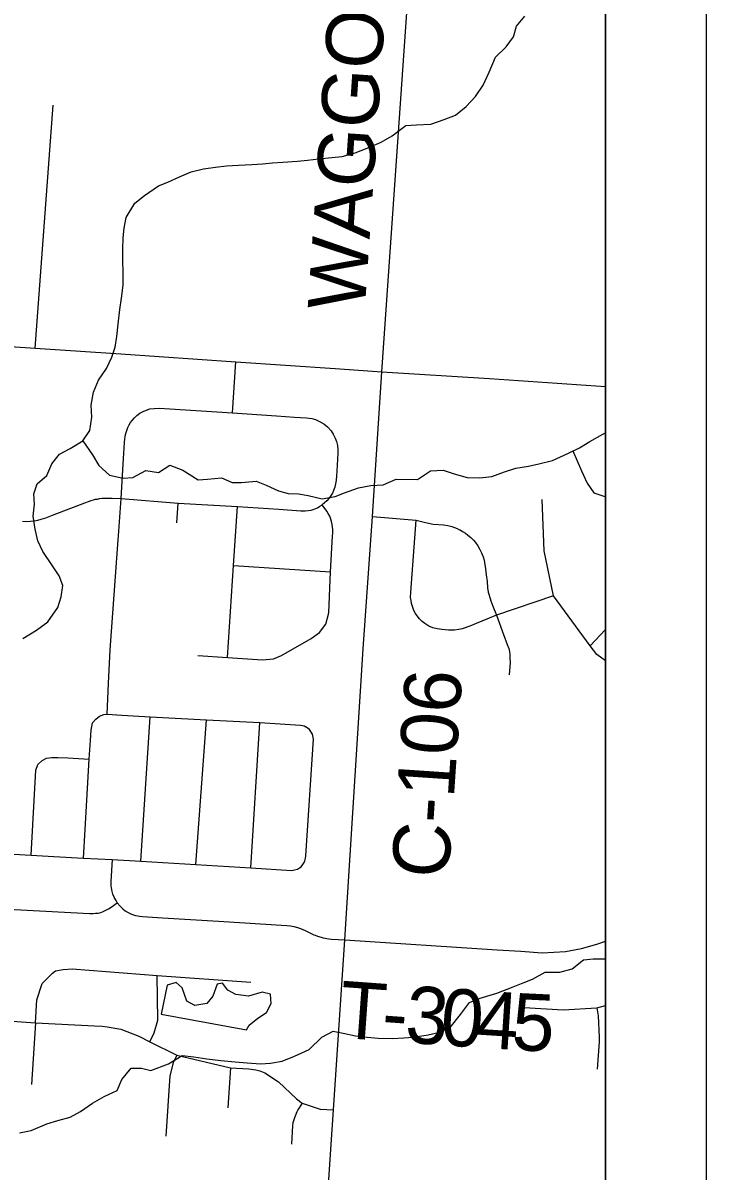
# Model space of a CAD drawing. Extents: x 208586767.6 to 208586821.4, y -134301046.9 to -134301022.9.
# Drawn here: x 208586784.249 to 208586784.928, y -134301030.351 to -134301029.209 of the extents above; entities that cross this region are included whole.
import ezdxf

# ---------------------------------------------------------------- set-up
doc = ezdxf.new("R2010")
doc.units = 0
for name, color, linetype in [('GM_X_Corporation', 7, 'Continuous'), ('GM_X_County_Road', 7, 'Continuous'), ('GM_X_County_Road_Text', 7, 'Continuous'), ('GM_X_Minor_Lake', 7, 'Continuous'), ('GM_X_Minor_River', 7, 'Continuous'), ('GM_X_Township_Road', 7, 'Continuous'), ('GM_X_Township_Road_Text', 7, 'Continuous'), ('SH_Data', 7, 'Continuous')]:
    doc.layers.add(name, color=color, linetype=linetype)

msp = doc.modelspace()

# ---------------------------------------------------------------- linework, layer by layer
at = {"layer": 'GM_X_Corporation'}
msp.add_lwpolyline([(208586780.4561, -134301030.8407), (208586784.8283, -134301030.8407), (208586784.8283, -134301027.3051), (208586784.2616, -134301027.2694), (208586783.9036, -134301027.2474), (208586783.5221, -134301027.2233), (208586782.8221, -134301027.178), (208586782.72, -134301027.1729), (208586782.648, -134301027.1691), (208586782.6378, -134301027.1684), (208586782.6086, -134301027.1669), (208586782.1685, -134301027.1422), (208586781.98, -134301027.1295), (208586781.8736, -134301027.1231), (208586781.8549, -134301027.122), (208586781.8329, -134301027.1207), (208586781.7344, -134301027.1148), (208586781.7056, -134301027.1139), (208586781.6677, -134301027.1118), (208586781.2713, -134301027.0897)], dxfattribs=at)
at = {"layer": 'GM_X_County_Road'}
for points in [[(208586784.6058, -134301029.5557), (208586784.6478, -134301028.9502), (208586784.6497, -134301028.9173)], [(208586783.2684, -134301029.5377), (208586783.3875, -134301029.5464), (208586783.5253, -134301029.5557), (208586783.5863, -134301029.5603), (208586783.6494, -134301029.5646), (208586783.6822, -134301029.5661), (208586783.7371, -134301029.5592), (208586783.7717, -134301029.5486), (208586783.7999, -134301029.5404), (208586783.842, -134301029.5277), (208586783.8725, -134301029.5192), (208586783.899, -134301029.5131), (208586783.925, -134301029.5105), (208586783.9583, -134301029.512), (208586783.9759, -134301029.5131), (208586784.0981, -134301029.5214), (208586784.1958, -134301029.5279), (208586784.261, -134301029.5322), (208586784.346, -134301029.5381), (208586784.4606, -134301029.5458), (208586784.5592, -134301029.5524), (208586784.6058, -134301029.5557), (208586784.7129, -134301029.5625), (208586784.8283, -134301029.5704)], [(208586784.555, -134301030.3295), (208586784.5576, -134301030.2902), (208586784.5689, -134301030.1211), (208586784.5873, -134301029.8315), (208586784.5965, -134301029.6999), (208586784.6058, -134301029.5557)], [(208586784.5262, -134301030.8407), (208586784.5315, -134301030.7681), (208586784.5315, -134301030.7336), (208586784.5353, -134301030.6564), (208586784.5412, -134301030.5475), (208586784.5437, -134301030.5064), (208586784.5449, -134301030.4836), (208586784.555, -134301030.3295)]]:
    msp.add_lwpolyline(points, dxfattribs=at)
at = {"layer": 'GM_X_Minor_Lake'}
for points in [[(208586784.4712, -134301030.2107), (208586784.4739, -134301030.2058), (208586784.4823, -134301030.199), (208586784.4911, -134301030.1933), (208586784.4957, -134301030.1843), (208586784.495, -134301030.1751), (208586784.4867, -134301030.1732), (208586784.473, -134301030.1769), (208586784.4605, -134301030.1753), (208586784.4525, -134301030.1711), (208586784.4472, -134301030.1642), (208586784.4419, -134301030.165), (208586784.4377, -134301030.1771), (208586784.4316, -134301030.1843), (208586784.4198, -134301030.1865), (208586784.4118, -134301030.1819), (208586784.407, -134301030.1689), (208586784.4013, -134301030.1636), (208586784.3922, -134301030.1662), (208586784.3863, -134301030.195)], [(208586784.3863, -134301030.195), (208586784.4712, -134301030.2107)]]:
    msp.add_lwpolyline(points, dxfattribs=at)
at = {"layer": 'GM_X_Minor_River'}
for points in [[(208586784.3404, -134301029.5314), (208586784.3423, -134301029.5208), (208586784.3435, -134301029.5083), (208586784.3452, -134301029.4938), (208586784.3467, -134301029.4825), (208586784.3483, -134301029.4696), (208586784.3484, -134301029.4567), (208586784.3481, -134301029.4453), (208586784.3482, -134301029.4339), (208586784.3486, -134301029.4225), (208586784.3495, -134301029.413), (208586784.3514, -134301029.4024), (208586784.3599, -134301029.3881), (208586784.3698, -134301029.3805), (208586784.3835, -134301029.3707), (208586784.393, -134301029.367), (208586784.4044, -134301029.3618), (208586784.4162, -134301029.3569), (208586784.4284, -134301029.3539), (208586784.4402, -134301029.3521), (208586784.4512, -134301029.351), (208586784.4633, -134301029.3503), (208586784.4766, -134301029.3497), (208586784.4872, -134301029.349), (208586784.4971, -134301029.3479), (208586784.5074, -134301029.3472), (208586784.5218, -134301029.3461), (208586784.5317, -134301029.3451), (208586784.5431, -134301029.344), (208586784.556, -134301029.3425), (208586784.5662, -134301029.3415), (208586784.5792, -134301029.3381), (208586784.5913, -134301029.3333), (208586784.605, -134301029.3273), (208586784.6161, -134301029.3209), (208586784.6298, -134301029.3107), (208586784.6401, -134301029.31), (208586784.6545, -134301029.3094), (208586784.6678, -134301029.3049), (208586784.6792, -134301029.3004), (208586784.6895, -134301029.2917), (208586784.6991, -134301029.2819), (208586784.7067, -134301029.2706), (208586784.7125, -134301029.2577), (208586784.7187, -134301029.2429), (208586784.7294, -134301029.2324), (208586784.7366, -134301029.2226), (208586784.7397, -134301029.212), (208586784.7481, -134301029.2018)], [(208586784.2486, -134301029.8211), (208586784.2623, -134301029.8129), (208586784.2734, -134301029.8046), (208586784.2833, -134301029.7902), (208586784.2868, -134301029.7796), (208586784.2884, -134301029.7686), (208586784.2847, -134301029.7587), (208586784.2783, -134301029.7488), (208586784.2685, -134301029.7347), (208586784.2636, -134301029.7241), (208586784.261, -134301029.7123), (208586784.2589, -134301029.6994), (208586784.2601, -134301029.6876), (208586784.2597, -134301029.6774), (208586784.2628, -134301029.6672), (208586784.2724, -134301029.6589), (208586784.2774, -134301029.6475), (208586784.285, -134301029.6377), (208586784.2957, -134301029.6321), (208586784.3083, -134301029.6245), (208586784.3152, -134301029.6143), (208586784.3172, -134301029.6011), (208586784.3165, -134301029.5889), (208586784.3188, -134301029.576), (208586784.3238, -134301029.5643), (208586784.3319, -134301029.5526), (208586784.3373, -134301029.5412), (208586784.3404, -134301029.5314)], [(208586784.3083, -134301029.6245), (208586784.3181, -134301029.6383), (208586784.3241, -134301029.6489), (208586784.335, -134301029.6585), (208586784.3483, -134301029.6616), (208586784.3582, -134301029.6609), (208586784.3711, -134301029.6541), (208586784.3836, -134301029.6561), (208586784.395, -134301029.6486), (208586784.4079, -134301029.6536), (208586784.423, -134301029.6632), (208586784.4325, -134301029.6625), (208586784.4462, -134301029.6614), (208586784.4568, -134301029.666), (208586784.4663, -134301029.6661), (208586784.4807, -134301029.6647), (208586784.4906, -134301029.6685), (208586784.503, -134301029.6743), (208586784.5125, -134301029.677), (208586784.5228, -134301029.6774), (208586784.5326, -134301029.679), (208586784.5463, -134301029.6821), (208586784.5592, -134301029.6799), (208586784.5687, -134301029.6762), (208586784.5824, -134301029.6713), (208586784.5949, -134301029.6691), (208586784.6071, -134301029.6684), (208586784.62, -134301029.6628), (208586784.6413, -134301029.663), (208586784.6542, -134301029.6543), (208586784.6668, -134301029.6536), (208586784.6777, -134301029.6575), (208586784.6906, -134301029.661), (208586784.7031, -134301029.6614), (208586784.7153, -134301029.66), (208586784.7278, -134301029.6555), (208586784.7389, -134301029.6518), (208586784.7518, -134301029.6496), (208586784.7621, -134301029.6474), (208586784.7754, -134301029.644), (208586784.7913, -134301029.6369), (208586784.8024, -134301029.6313), (208586784.8127, -134301029.6253), (208586784.8256, -134301029.6178), (208586784.8283, -134301029.6164)], [(208586784.7959, -134301029.6346), (208586784.8045, -134301029.6544), (208586784.8101, -134301029.6666), (208586784.8165, -134301029.6761), (208586784.8275, -134301029.68), (208586784.8283, -134301029.6797)], [(208586784.2452, -134301030.3129), (208586784.2569, -134301030.3107), (208586784.2725, -134301030.304), (208586784.2836, -134301030.3006), (208586784.2957, -134301030.2973), (208586784.306, -134301030.2917), (208586784.3178, -134301030.2834), (208586784.3296, -134301030.277), (208586784.3426, -134301030.271), (208586784.3472, -134301030.26), (208586784.3564, -134301030.2487), (208586784.3666, -134301030.2488), (208586784.3761, -134301030.2511), (208586784.3936, -134301030.2444), (208586784.4073, -134301030.2361), (208586784.4187, -134301030.2373), (208586784.4316, -134301030.2393), (208586784.4456, -134301030.2409), (208586784.46, -134301030.2425), (208586784.4718, -134301030.2433), (208586784.4851, -134301030.2445), (208586784.4949, -134301030.2438), (208586784.5067, -134301030.2416), (208586784.5189, -134301030.2368), (208586784.5334, -134301030.23), (208586784.546, -134301030.218), (208586784.5574, -134301030.2119), (208586784.5672, -134301030.2139), (208586784.5797, -134301030.2166), (208586784.5911, -134301030.2178), (208586784.6021, -134301030.2187), (208586784.6162, -134301030.2191), (208586784.6276, -134301030.2184), (208586784.637, -134301030.2177), (208586784.6519, -134301030.2155), (208586784.6617, -134301030.2133), (208586784.6739, -134301030.2081), (208586784.6839, -134301030.1952), (208586784.6931, -134301030.1835), (208586784.7037, -134301030.179), (208586784.7201, -134301030.1742), (208586784.7364, -134301030.1679), (208586784.7463, -134301030.1637), (208586784.7558, -134301030.16), (208586784.7684, -134301030.1532), (208586784.7828, -134301030.1533), (208586784.795, -134301030.15), (208586784.8064, -134301030.1409), (208586784.8159, -134301030.1399), (208586784.8277, -134301030.1399), (208586784.8283, -134301030.1399)]]:
    msp.add_lwpolyline(points, dxfattribs=at)
at = {"layer": 'GM_X_Township_Road'}
for p, q in [((208586784.261, -134301029.5322), (208586784.2789, -134301029.2905)), ((208586784.4572, -134301029.5965), (208586784.4606, -134301029.5458)), ((208586784.4019, -134301029.7061), (208586784.4031, -134301029.6864)), ((208586784.4583, -134301029.7484), (208586784.5547, -134301029.7549)), ((208586784.8131, -134301029.8285), (208586784.8283, -134301029.8122)), ((208586784.3324, -134301029.8963), (208586784.3339, -134301029.8658)), ((208586784.366, -134301030.0426), (208586784.3754, -134301029.899)), ((208586784.4208, -134301030.046), (208586784.4312, -134301029.902)), ((208586784.4756, -134301030.0494), (208586784.4845, -134301029.9048)), ((208586784.3823, -134301030.1565), (208586784.4754, -134301030.163)), ((208586784.2612, -134301030.2037), (208586784.2574, -134301030.2651)), ((208586784.4551, -134301030.2483), (208586784.4525, -134301030.288))]:
    msp.add_line(p, q, dxfattribs=at)
for points in [[(208586784.3597, -134301029.6016), (208586784.3622, -134301029.5993), (208586784.3651, -134301029.5971), (208586784.369, -134301029.595), (208586784.3749, -134301029.5928), (208586784.3792, -134301029.5922), (208586784.3847, -134301029.592), (208586784.3948, -134301029.5927), (208586784.4572, -134301029.5965), (208586784.501, -134301029.5995), (208586784.5188, -134301029.6008), (208586784.5307, -134301029.6016), (208586784.5361, -134301029.6023), (208586784.5399, -134301029.6032), (208586784.5439, -134301029.6051), (208586784.5479, -134301029.6075), (208586784.5517, -134301029.6105), (208586784.5553, -134301029.6144), (208586784.5575, -134301029.6179), (208586784.5595, -134301029.6217), (208586784.5607, -134301029.6253), (208586784.5615, -134301029.629), (208586784.562, -134301029.6333), (208586784.562, -134301029.6369), (208586784.5609, -134301029.6546), (208586784.5606, -134301029.6593), (208586784.5602, -134301029.6636), (208586784.5598, -134301029.6673), (208586784.5589, -134301029.6705), (208586784.5578, -134301029.6738), (208586784.5566, -134301029.6766), (208586784.5553, -134301029.6786), (208586784.5535, -134301029.6816), (208586784.5511, -134301029.6843), (208586784.5464, -134301029.6883)], [(208586784.3464, -134301029.682), (208586784.3489, -134301029.642), (208586784.3496, -134301029.6316), (208586784.3499, -134301029.6263), (208586784.3502, -134301029.6224), (208586784.3504, -134301029.6205), (208586784.3508, -134301029.6183), (208586784.3513, -134301029.6162), (208586784.352, -134301029.6141), (208586784.3531, -134301029.6113), (208586784.3544, -134301029.6087), (208586784.3558, -134301029.6064), (208586784.3573, -134301029.6043), (208586784.3597, -134301029.6016)], [(208586784.2483, -134301029.7045), (208586784.2522, -134301029.7046), (208586784.2563, -134301029.7045), (208586784.2602, -134301029.7041), (208586784.2637, -134301029.7034), (208586784.2668, -134301029.7026), (208586784.2716, -134301029.701), (208586784.2781, -134301029.6985), (208586784.3102, -134301029.6861), (208586784.3138, -134301029.6847), (208586784.3165, -134301029.6838), (208586784.3188, -134301029.6831), (208586784.3208, -134301029.6827), (208586784.3229, -134301029.6824), (208586784.3249, -134301029.682), (208586784.3277, -134301029.6816), (208586784.3307, -134301029.6815), (208586784.3337, -134301029.6814), (208586784.3376, -134301029.6815), (208586784.3464, -134301029.682), (208586784.4031, -134301029.6864), (208586784.4623, -134301029.6898), (208586784.5033, -134301029.6926), (208586784.5251, -134301029.6943), (208586784.5295, -134301029.6943), (208586784.5325, -134301029.6939), (208586784.5356, -134301029.6934), (208586784.5385, -134301029.6924), (208586784.5417, -134301029.691), (208586784.5442, -134301029.6896), (208586784.5464, -134301029.6883)], [(208586784.3434, -134301029.723), (208586784.3437, -134301029.7189), (208586784.3464, -134301029.682)], [(208586784.8283, -134301029.8435), (208586784.8195, -134301029.8372), (208586784.8131, -134301029.8285), (208586784.7764, -134301029.7786), (208586784.7673, -134301029.7339), (208586784.7654, -134301029.6828)], [(208586784.4228, -134301029.838), (208586784.4521, -134301029.84), (208586784.4871, -134301029.8424), (208586784.4979, -134301029.8413), (208586784.5058, -134301029.8381), (208586784.5354, -134301029.8211), (208586784.5439, -134301029.8153), (208586784.55, -134301029.8068), (208586784.5529, -134301029.7956), (208586784.5547, -134301029.7549), (208586784.5568, -134301029.7193), (208586784.557, -134301029.7159), (208586784.5571, -134301029.713), (208586784.5568, -134301029.71), (208586784.5563, -134301029.7077), (208586784.5557, -134301029.7049), (208586784.555, -134301029.7024), (208586784.5539, -134301029.6994), (208586784.5525, -134301029.6969), (208586784.5509, -134301029.6945), (208586784.5464, -134301029.6883)], [(208586784.4521, -134301029.84), (208586784.4583, -134301029.7484), (208586784.4623, -134301029.6898)], [(208586784.5965, -134301029.6999), (208586784.6398, -134301029.7034), (208586784.6492, -134301029.7056)], [(208586784.7764, -134301029.7786), (208586784.7197, -134301029.7981), (208586784.7052, -134301029.8039), (208586784.6995, -134301029.8061), (208586784.6948, -134301029.8081), (208586784.6886, -134301029.8105), (208586784.6857, -134301029.8115), (208586784.6825, -134301029.8123), (208586784.6781, -134301029.8128), (208586784.672, -134301029.8129), (208586784.6654, -134301029.8123), (208586784.6609, -134301029.8117), (208586784.6565, -134301029.8105), (208586784.6524, -134301029.8088), (208586784.6485, -134301029.8063), (208586784.6458, -134301029.8042), (208586784.6433, -134301029.8016), (208586784.6408, -134301029.7986), (208586784.6393, -134301029.7963), (208586784.6377, -134301029.7932), (208586784.6362, -134301029.7894), (208586784.6354, -134301029.7865), (208586784.6349, -134301029.7835), (208586784.6344, -134301029.7804), (208586784.6346, -134301029.7751), (208586784.6398, -134301029.7034)], [(208586784.6492, -134301029.7056), (208586784.6567, -134301029.7074), (208586784.6671, -134301029.7081), (208586784.6713, -134301029.7089), (208586784.6753, -134301029.7098), (208586784.6808, -134301029.7117), (208586784.683, -134301029.7129), (208586784.6836, -134301029.7132), (208586784.6861, -134301029.7146), (208586784.689, -134301029.7165), (208586784.6914, -134301029.7183), (208586784.6944, -134301029.7208), (208586784.6969, -134301029.7233), (208586784.6988, -134301029.7256), (208586784.7013, -134301029.729), (208586784.7034, -134301029.7325), (208586784.705, -134301029.736), (208586784.7066, -134301029.7399), (208586784.7075, -134301029.7433), (208586784.708, -134301029.7454), (208586784.7088, -134301029.7518), (208586784.7096, -134301029.7578), (208586784.7104, -134301029.7646), (208586784.711, -134301029.7708), (208586784.7117, -134301029.775), (208586784.7125, -134301029.7782), (208586784.7142, -134301029.7837), (208586784.7162, -134301029.7891), (208586784.7197, -134301029.7981)], [(208586784.3339, -134301029.8658), (208586784.3356, -134301029.8324), (208586784.3434, -134301029.723)], [(208586784.7197, -134301029.7981), (208586784.7268, -134301029.8173), (208586784.7306, -134301029.827), (208586784.732, -134301029.8312), (208586784.7327, -134301029.8341), (208586784.7332, -134301029.8374), (208586784.7332, -134301029.8407), (208586784.7333, -134301029.8451), (208586784.7323, -134301029.8574)], [(208586784.3089, -134301030.0396), (208586784.3106, -134301030.0111), (208586784.3147, -134301029.9413), (208586784.3159, -134301029.9228), (208586784.3165, -134301029.9123), (208586784.3178, -134301029.9051), (208586784.3211, -134301029.9014), (208586784.325, -134301029.8983), (208586784.3293, -134301029.8967), (208586784.3324, -134301029.8963)], [(208586784.3324, -134301029.8963), (208586784.3472, -134301029.8973), (208586784.3754, -134301029.899), (208586784.4312, -134301029.902), (208586784.4845, -134301029.9048), (208586784.5248, -134301029.9074), (208586784.5268, -134301029.9078), (208586784.5284, -134301029.9082), (208586784.5295, -134301029.9087)], [(208586784.5254, -134301030.0482), (208586784.5273, -134301030.0461), (208586784.5285, -134301030.0442), (208586784.5293, -134301030.0423), (208586784.5299, -134301030.0397), (208586784.5301, -134301030.0373), (208586784.5378, -134301029.9212), (208586784.5369, -134301029.9165), (208586784.5339, -134301029.9118), (208586784.5295, -134301029.9087)], [(208586784.2569, -134301030.0366), (208586784.2616, -134301029.9523), (208586784.2637, -134301029.9464), (208586784.2678, -134301029.9425), (208586784.2721, -134301029.9404), (208586784.2774, -134301029.9396), (208586784.2834, -134301029.9396), (208586784.2933, -134301029.9398), (208586784.3147, -134301029.9413)], [(208586784.1509, -134301030.0527), (208586784.1554, -134301030.0465), (208586784.1606, -134301030.042), (208586784.1655, -134301030.0379), (208586784.1719, -134301030.035), (208586784.1784, -134301030.0332), (208586784.1865, -134301030.0327), (208586784.2569, -134301030.0366), (208586784.2794, -134301030.0381), (208586784.3089, -134301030.0396), (208586784.3374, -134301030.0411), (208586784.366, -134301030.0426), (208586784.4208, -134301030.046), (208586784.4756, -134301030.0494), (208586784.5163, -134301030.0519), (208586784.519, -134301030.0515), (208586784.5218, -134301030.0506), (208586784.5238, -134301030.0495), (208586784.5254, -134301030.0482)], [(208586784.3374, -134301030.0411), (208586784.3362, -134301030.0629), (208586784.3361, -134301030.0654), (208586784.3362, -134301030.0674), (208586784.3364, -134301030.0691), (208586784.3367, -134301030.071), (208586784.3372, -134301030.073), (208586784.3379, -134301030.0755), (208586784.339, -134301030.0779), (208586784.3399, -134301030.0798), (208586784.3411, -134301030.0819), (208586784.3425, -134301030.0841), (208586784.3453, -134301030.0875), (208586784.348, -134301030.0901), (208586784.3506, -134301030.092), (208586784.3534, -134301030.0938), (208586784.3569, -134301030.0954), (208586784.3608, -134301030.0968), (208586784.363, -134301030.0972), (208586784.3648, -134301030.0976), (208586784.3676, -134301030.0979), (208586784.3877, -134301030.0991), (208586784.4433, -134301030.1024), (208586784.5113, -134301030.1066), (208586784.5148, -134301030.1071), (208586784.5181, -134301030.1078), (208586784.5219, -134301030.1088), (208586784.5237, -134301030.1094), (208586784.5265, -134301030.1104), (208586784.5301, -134301030.112), (208586784.5335, -134301030.1138), (208586784.5361, -134301030.1151), (208586784.538, -134301030.1159), (208586784.5395, -134301030.1165), (208586784.5418, -134301030.1174), (208586784.5453, -134301030.1184), (208586784.5473, -134301030.1189), (208586784.5494, -134301030.1194), (208586784.5511, -134301030.1197), (208586784.553, -134301030.1199), (208586784.5557, -134301030.1202), (208586784.5689, -134301030.1211)], [(208586784.1469, -134301030.0857), (208586784.315, -134301030.0949), (208586784.3186, -134301030.0949), (208586784.321, -134301030.0946), (208586784.3235, -134301030.0943), (208586784.3261, -134301030.0937), (208586784.3279, -134301030.093), (208586784.3299, -134301030.0923), (208586784.3318, -134301030.0913), (208586784.334, -134301030.0901), (208586784.3364, -134301030.0885), (208586784.3425, -134301030.0841)], [(208586784.5689, -134301030.1211), (208586784.7204, -134301030.131), (208586784.7439, -134301030.1324), (208586784.7653, -134301030.1338), (208586784.7885, -134301030.1327), (208586784.8045, -134301030.1297), (208586784.8195, -134301030.1253), (208586784.8283, -134301030.1222)], [(208586784.2612, -134301030.2037), (208586784.2626, -134301030.1808), (208586784.2678, -134301030.1643), (208586784.278, -134301030.154), (208586784.2813, -134301030.1517), (208586784.2888, -134301030.1504), (208586784.2977, -134301030.1498), (208586784.3823, -134301030.1565)], [(208586784.375, -134301030.2224), (208586784.3794, -134301030.2136), (208586784.3828, -134301030.2008), (208586784.3823, -134301030.1565)], [(208586784.7474, -134301030.1883), (208586784.7861, -134301030.1907), (208586784.8195, -134301030.1886), (208586784.8283, -134301030.1862)], [(208586784.1403, -134301030.1951), (208586784.2007, -134301030.1992), (208586784.2612, -134301030.2037)], [(208586784.8195, -134301030.1886), (208586784.8208, -134301030.1967), (208586784.8221, -134301030.218), (208586784.8221, -134301030.2191)], [(208586784.2612, -134301030.2037), (208586784.3199, -134301030.2065), (208586784.3274, -134301030.207), (208586784.3324, -134301030.2077), (208586784.346, -134301030.21), (208586784.364, -134301030.2169), (208586784.375, -134301030.2224), (208586784.402, -134301030.2359), (208586784.4551, -134301030.2483), (208586784.4736, -134301030.2495), (208586784.4803, -134301030.2503), (208586784.4845, -134301030.2515), (208586784.4895, -134301030.2532), (208586784.503, -134301030.2623), (208586784.521, -134301030.2791), (208586784.5265, -134301030.2834), (208586784.5444, -134301030.2894), (208586784.5576, -134301030.2902)], [(208586784.8221, -134301030.2191), (208586784.822, -134301030.2224), (208586784.8201, -134301030.2498)], [(208586784.402, -134301030.2359), (208586784.3982, -134301030.2435), (208586784.3948, -134301030.2562), (208586784.3909, -134301030.3163)], [(208586784.5265, -134301030.2834), (208586784.5223, -134301030.29), (208586784.5211, -134301030.2921), (208586784.5189, -134301030.2981), (208586784.5173, -134301030.3031), (208586784.517, -134301030.3058), (208586784.5159, -134301030.3243)]]:
    msp.add_lwpolyline(points, dxfattribs=at)
at = {"layer": 'SH_Data'}
for p, q in [((208586784.9283, -134301023.9407), (208586784.9283, -134301030.9407)), ((208586784.8283, -134301024.0407), (208586784.8283, -134301030.8407))]:
    msp.add_line(p, q, dxfattribs=at)

# ---------------------------------------------------------------- texts
at = {"layer": 'GM_X_County_Road_Text'}
for s, rotation, p in [('WAGGONER', 86.1074, (208586784.5887, -134301029.4959)), ('C-106', 86.1494, (208586784.672, -134301030.0607))]:
    msp.add_text(s, height=0.05682, rotation=rotation, dxfattribs=at).set_placement(p)
at = {"layer": 'GM_X_Township_Road_Text'}
for s, rotation, p in [('T', 355.8606, (208586784.5622, -134301030.2183)), ('3', 355.8792, (208586784.6279, -134301030.223)), ('0', 355.9759, (208586784.6629, -134301030.2255)), ('4', 356.2908, (208586784.6982, -134301030.228)), ('5', 357.2495, (208586784.7342, -134301030.2304)), ('-', 355.8706, (208586784.6046, -134301030.2213))]:
    msp.add_text(s, height=0.0568, rotation=rotation, dxfattribs=at).set_placement(p)

doc.saveas('drawing.dxf')
